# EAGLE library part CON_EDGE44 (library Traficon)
US card edge connector Wire wrap connector Farnell 145-148 RS-online 483-871 If you still can get the BLUE connector: use the BLUE variant. The BLACK version has wider pins, which makes it unusable on a print for 230Vac. So if you need 110Vac or 230Vac signals on this connector, you MUST use the BLUE variant.
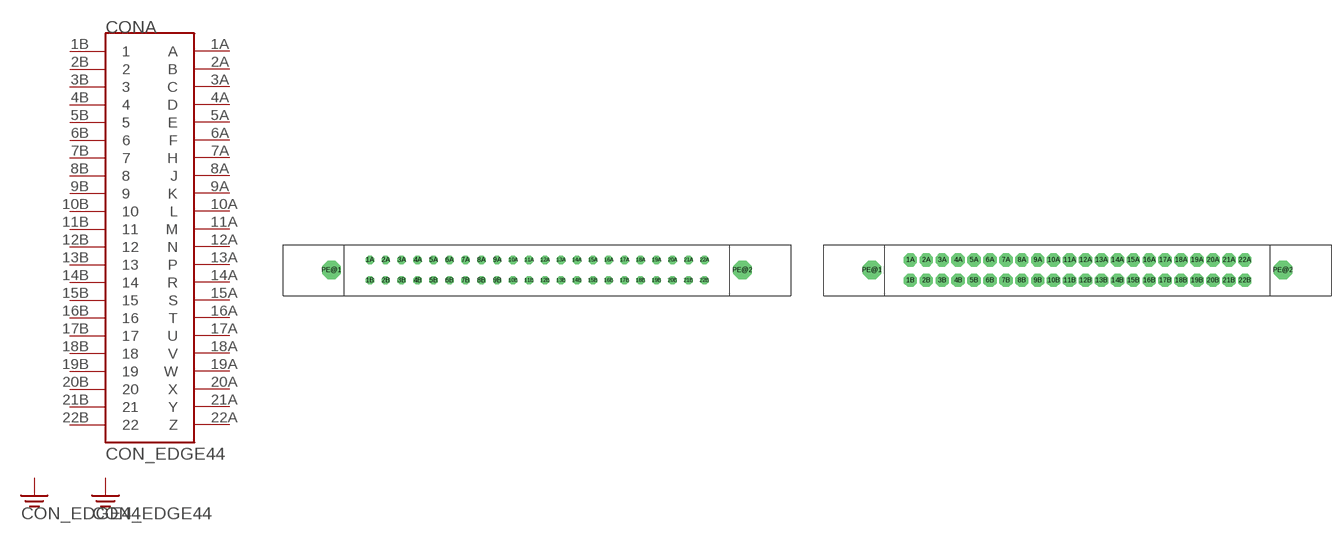
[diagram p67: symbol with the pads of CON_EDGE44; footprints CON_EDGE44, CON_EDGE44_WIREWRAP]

Designator prefix CON; gates A=CARD_EDGE_44P G$2=PE G$3=PE

## CON_EDGE44-BLUE  [CON_EDGE44]
1A  A:A
1B  A:1
2A  A:B
2B  A:2
3A  A:C
3B  A:3
4A  A:D
4B  A:4
5A  A:E
5B  A:5
6A  A:F
6B  A:6
7A  A:H
7B  A:7
8A  A:J
8B  A:8
9A  A:K
9B  A:9
10A  A:L
10B  A:10
11A  A:M
11B  A:11
12A  A:N
12B  A:12
13A  A:P
13B  A:13
14A  A:R
14B  A:14
15A  A:S
15B  A:15
16A  A:T
16B  A:16
17A  A:U
17B  A:17
18A  A:V
18B  A:18
19A  A:W
19B  A:19
20A  A:X
20B  A:20
21A  A:Y
21B  A:21
22A  A:Z
22B  A:22
PE@1  G$2:PE  sup
PE@2  G$3:PE  sup

## CON_EDGE44-BLACK  [CON_EDGE44_WIREWRAP]
Pads as for CON_EDGE44

## CON_EDGE44-90°  [CON_EDGE44_90°]
1  A:1
2  A:2
3  A:3
4  A:4
5  A:5
6  A:6
7  A:7
8  A:8
9  A:9
10  A:10
11  A:11
12  A:12
13  A:13
14  A:14
15  A:15
16  A:16
17  A:17
18  A:18
19  A:19
20  A:20
21  A:21
22  A:22
A  A:A
B  A:B
C  A:C
D  A:D
E  A:E
F  A:F
H  A:H
J  A:J
K  A:K
L  A:L
M  A:M
N  A:N
P  A:P
PE@1  G$2:PE  sup
PE@2  G$3:PE  sup
R  A:R
S  A:S
T  A:T
U  A:U
V  A:V
W  A:W
X  A:X
Y  A:Y
Z  A:Z

## Footprint CON_EDGE44 (pad centres in mm)
drill 1.4 octagon: 1A -41.91,2.54; 1B -41.91,-2.54; 2A -37.948,2.54; 2B -37.948,-2.54; 3A -33.985,2.54; 3B -33.985,-2.54; 4A -30.023,2.54; 4B -30.023,-2.54; 5A -26.06,2.54; 5B -26.06,-2.54; 6A -22.098,2.54; 6B -22.098,-2.54; 7A -18.136,2.54; 7B -18.136,-2.54; 8A -14.173,2.54; 8B -14.173,-2.54; 9A -10.211,2.54; 9B -10.211,-2.54; 10A -6.248,2.54; 10B -6.248,-2.54; 11A -2.286,2.54; 11B -2.286,-2.54; 12A 1.676,2.54; 12B 1.676,-2.54; 13A 5.639,2.54; 13B 5.639,-2.54; 14A 9.601,2.54; 14B 9.601,-2.54; 15A 13.564,2.54; 15B 13.564,-2.54; 16A 17.526,2.54; 16B 17.526,-2.54; 17A 21.488,2.54; 17B 21.488,-2.54; 18A 25.451,2.54; 18B 25.451,-2.54; 19A 29.413,2.54; 19B 29.413,-2.54; 20A 33.376,2.54; 20B 33.376,-2.54; 21A 37.338,2.54; 21B 37.338,-2.54; 22A 41.3,2.54; 22B 41.3,-2.54
drill 3.556 octagon: PE@1 -51.435,0; PE@2 50.8,0

## Footprint CON_EDGE44_WIREWRAP (pad centres in mm)
drill 2.3 octagon: 1A -41.91,2.54; 1B -41.91,-2.54; 2A -37.948,2.54; 2B -37.948,-2.54; 3A -33.985,2.54; 3B -33.985,-2.54; 4A -30.023,2.54; 4B -30.023,-2.54; 5A -26.06,2.54; 5B -26.06,-2.54; 6A -22.098,2.54; 6B -22.098,-2.54; 7A -18.136,2.54; 7B -18.136,-2.54; 8A -14.173,2.54; 8B -14.173,-2.54; 9A -10.211,2.54; 9B -10.211,-2.54; 10A -6.248,2.54; 10B -6.248,-2.54; 11A -2.286,2.54; 11B -2.286,-2.54; 12A 1.676,2.54; 12B 1.676,-2.54; 13A 5.639,2.54; 13B 5.639,-2.54; 14A 9.601,2.54; 14B 9.601,-2.54; 15A 13.564,2.54; 15B 13.564,-2.54; 16A 17.526,2.54; 16B 17.526,-2.54; 17A 21.488,2.54; 17B 21.488,-2.54; 18A 25.451,2.54; 18B 25.451,-2.54; 19A 29.413,2.54; 19B 29.413,-2.54; 20A 33.376,2.54; 20B 33.376,-2.54; 21A 37.338,2.54; 21B 37.338,-2.54; 22A 41.3,2.54; 22B 41.3,-2.54
drill 3.556 octagon: PE@1 -51.435,0; PE@2 50.8,0

## Footprint CON_EDGE44_90° (pad centres in mm)
drill 1.4 octagon: 1 41.3,2.54; 2 37.338,2.54; 3 33.376,2.54; 4 29.413,2.54; 5 25.451,2.54; 6 21.488,2.54; 7 17.526,2.54; 8 13.564,2.54; 9 9.601,2.54; 10 5.639,2.54; 11 1.676,2.54; 12 -2.286,2.54; 13 -6.248,2.54; 14 -10.211,2.54; 15 -14.173,2.54; 16 -18.136,2.54; 17 -22.098,2.54; 18 -26.06,2.54; 19 -30.023,2.54; 20 -33.985,2.54; 21 -37.948,2.54; 22 -41.91,2.54; A 41.3,-2.54; B 37.338,-2.54; C 33.376,-2.54; D 29.413,-2.54; E 25.451,-2.54; F 21.488,-2.54; H 17.526,-2.54; J 13.564,-2.54; K 9.601,-2.54; L 5.639,-2.54; M 1.676,-2.54; N -2.286,-2.54; P -6.248,-2.54; R -10.211,-2.54; S -14.173,-2.54; T -18.136,-2.54; U -22.098,-2.54; V -26.06,-2.54; W -30.023,-2.54; X -33.985,-2.54; Y -37.948,-2.54; Z -41.91,-2.54
drill 2.5 octagon: PE@1 -51.435,-7.62; PE@2 50.8,-7.62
